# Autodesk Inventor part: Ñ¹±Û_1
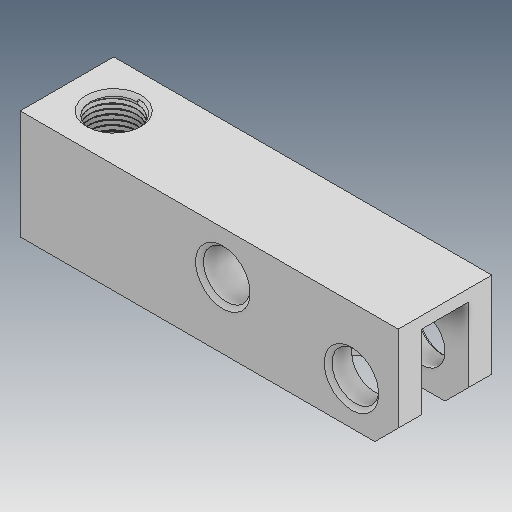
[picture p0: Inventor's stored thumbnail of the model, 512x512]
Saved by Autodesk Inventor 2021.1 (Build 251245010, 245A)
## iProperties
Created: 2019-04
Part Number: Ñ¹±Û_1
Material: Ogólny
Document SubType Name: Modeling
Designer: user
Density: 1 g/cm^3
Appearance: Domyślna
Author: user
Revision Number: ÈÎºÎ
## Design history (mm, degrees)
feature "ÊäÈë1"
node "Bryła1"
